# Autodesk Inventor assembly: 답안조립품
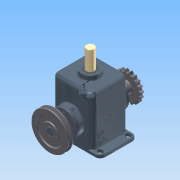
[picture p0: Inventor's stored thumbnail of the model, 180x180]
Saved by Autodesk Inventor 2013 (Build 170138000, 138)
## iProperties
Created: 2015-03
Part Number: 답안조립품
Document SubType Name: Assembly
Designer: Administrator
Author: Administrator
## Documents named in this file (15)
- C:\Documents and Settings\Administrator\바탕 화면\350305V1038\답안조립품.iam
- C:\Documents and Settings\Administrator\바탕 화면\350305V1038\본체.ipt
- C:\Documents and Settings\Administrator\바탕 화면\350305V1038\베어링 6205.ipt
- C:\Documents and Settings\Administrator\바탕 화면\350305V1038\편심축.ipt
- C:\Documents and Settings\Administrator\바탕 화면\350305V1038\멈춤링.ipt
- C:\Documents and Settings\Administrator\바탕 화면\350305V1038\커버.ipt
- C:\Documents and Settings\Administrator\바탕 화면\350305V1038\키 8x8.ipt
- C:\Documents and Settings\Administrator\바탕 화면\350305V1038\오일실.ipt
- C:\Documents and Settings\Administrator\바탕 화면\350305V1038\슬라이드.ipt
- C:\Documents and Settings\Administrator\바탕 화면\350305V1038\부시.ipt
- C:\Documents and Settings\Administrator\바탕 화면\350305V1038\M4x0.5.ipt
- C:\Documents and Settings\Administrator\바탕 화면\350305V1038\V-벨트풀리.ipt
- C:\Documents and Settings\Administrator\바탕 화면\350305V1038\체인 스프로킷.ipt
- C:\Documents and Settings\Administrator\바탕 화면\350305V1038\멈춤나사 M5x0.5.ipt
- C:\Documents and Settings\Administrator\바탕 화면\350305V1038\스프링 - [가변].ipt
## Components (8 placed, 3 different names)
1. V-벨트풀리:1 — 플러쉬:1, 각도:3
2. 5-체인 스프로킷:1 — 플러쉬:2, 각도:4
3. M4x0.5:1
4. M4x0.5:3
5. M4x0.5:4
6. M4x0.5:2
7. M4x0.5:5
8. M4x0.5:6
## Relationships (4: Flush 2, Angle 2)
- 플러쉬:1 [Flush]: V-벨트풀리:1
- 플러쉬:2 [Flush]: 5-체인 스프로킷:1
- 각도:3 [Angle]: V-벨트풀리:1
- 각도:4 [Angle]: 5-체인 스프로킷:1
